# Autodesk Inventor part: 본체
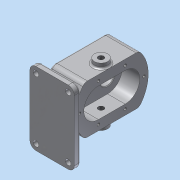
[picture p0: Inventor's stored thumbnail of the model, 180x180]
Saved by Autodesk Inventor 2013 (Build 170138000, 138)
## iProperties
Created: 2019-03
Part Number: 본체
Material: 알루미늄 6061
Document SubType Name: Modeling
Designer: Administrator
Mass: 1194.85 g
Surface Area: 724.416 cm^2
Volume: 440.905 cm^3
Density: 2.71 g/cm^3
Author: Administrator
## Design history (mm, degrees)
sketch "스케치1"
  geometry: L1 (26.5, -60)-(-26.5, -60); L2 (-36.5, -50)-(-36.5, 50); L3 (-26.5, 60)-(26.5, 60); L4 (36.5, 50)-(36.5, -50); A1 r 10 centre (26.5, -50) between (26.5, -60) and (36.5, -50); A2 r 10 centre (26.5, 50) between (36.5, 50) and (26.5, 60); A3 r 10 centre (-26.5, 50) between (-26.5, 60) and (-36.5, 50); A4 r 10 centre (-26.5, -50) between (-36.5, -50) and (-26.5, -60); 6 further points
  constraints: 8 end point, 8 point on circle, 8 tangent, 6 point on line, 4 centre point, 3 equal radius, 2 midpoint, 2 parallel, 1 horizontal, 1 horizontal alignment, 1 perpendicular, 1 vertical alignment
  dimensions: "d0" = 73 distance of point (-36.5, 60) point (36.5, 60); "d1" = 120 distance of point (-36.5, -60) point (-36.5, 60); "d2" = 10 radius of A1
extrude "돌출1" new body sketch "스케치1" distance "d4" = 10; taper "d5" = 0 deg
hole "구멍1" diameter "d8" = 9; stored, may be unused: countersink angle "d12" = 90 deg, drill point angle "d14" = 118 deg; dims "d6" = 10, "d7" = 10, "d9" = 6, "d10" = 4, "d11" = 2, "d13" = 8
hole "구멍2" diameter "d17" = 9; stored, may be unused: countersink angle "d21" = 90 deg, drill point angle "d23" = 118 deg; dims "d15" = 10, "d16" = 10, "d18" = 6, "d19" = 4, "d20" = 2, "d22" = 8
sketch "스케치2"
  geometry: L1 (36.5, -50)-(36.5, 50) reference; 2 further points
  constraints: 1 horizontal alignment, 1 other
  dimensions: "d24" = 10 distance from line of L1 point (26.5, 0)
feature "엠보싱1" sketch "스케치2" dims "d0" = 73, "d1" = 120, "d2" = 10, "d18" = 6, "d25" = 0.5, "d26" = 0
sketch "스케치3"
  geometry: L1 (24.115, 10.5)-(24.529, 10.5) reference; L2 (24.529, 10.5)-(24.529, 10) reference; L3 (24.529, 10)-(36.5, 10) reference; L4 (36.5, 10)-(36.5, 0) reference; L5 (36.5, 0)-(-36.5, 0) reference; L6 (-36.5, 0)-(-36.5, 10) reference; L7 (-36.5, 10)-(24.115, 10) reference; L8 (24.115, 10)-(24.115, 10.5) reference; L9 (-36.5, 10)-(6.5, 10); L10 (6.5, 10)-(6.5, 25); L11 (6.5, 25)-(-36.5, 25); L12 (-36.5, 25)-(-36.5, 10); 1 further point
  constraints: 8 end point, 2 parallel, 1 horizontal, 1 perpendicular
  dimensions: "d27" = 43 distance of L11.end L10.end; "d42" = 15 distance of L9.end L10.end
extrude "돌출2" join sketch "스케치3" distance "d28" = 6; taper "d30" = 0 deg; dims "d29" = 6, "d31" = 0
fillet "모깎기1" dims "d32" = 6
fillet "모깎기2" dims "d33" = 3
sketch "스케치4"
  geometry: L1 (0, 0)-(100, 0) reference; L2 (44, 25)-(56, 25) reference; L3 (90, 121.704)-(90, 41.704); L4 (10, 41.704)-(10, 121.704); A1 r 60 centre (50, 81.704) between (86, 129.704) and (14, 129.704); A2 r 10 centre (20, 121.704) between (14, 129.704) and (10, 121.704); A3 r 10 centre (80, 121.704) between (90, 121.704) and (86, 129.704); A4 r 10 centre (20, 41.704) between (10, 41.704) and (14, 33.704); A5 r 60 centre (50, 81.704) between (14, 33.704) and (86, 33.704); A6 r 10 centre (80, 41.704) between (86, 33.704) and (90, 41.704); 6 further points
  constraints: 13 point on circle, 6 centre point, 4 end point, 4 tangent, 2 midpoint, 1 coincident, 1 equal radius, 1 parallel
  dimensions: "d36" = 120 diameter of A1; "d37" = 10 radius of A2
extrude "돌출3" join sketch "스케치4" distance "d40" = 53; taper "d41" = 0 deg
fillet "모깎기3" dims "d43" = 3
fillet "모깎기4" dims "d44" = 3
sketch "스케치5"
  geometry: L1 (-26, 103.704)-(-26, 59.704); L2 (-74, 59.704)-(-74, 103.704); L3 (-100, 0)-(0, 0) reference; A1 r 24 centre (-50, 103.704) between (-26, 103.704) and (-74, 103.704); A2 r 24 centre (-50, 59.704) between (-74, 59.704) and (-26, 59.704); A3 r 60 centre (-50, 81.704) between (-86, 33.704) and (-14, 33.704) reference; 4 further points
  constraints: 4 end point, 4 point on circle, 3 midpoint, 2 centre point, 1 parallel, 1 vertical alignment
  dimensions: "d47" = 44 distance of L1.end L1.start; "d48" = 24 radius of A1; "d49" = 24 radius of A2; "d51" = 48 distance between parallel lines of L1 L2; "d92" = 22 distance of A1.centre A3.centre
extrude "돌출4" cut sketch "스케치5" distance "d54" = 29; taper "d55" = 0 deg
hole "구멍3" diameter "d59" = 25; stored, may be unused: countersink angle "d63" = 90 deg, drill point angle "d65" = 0 deg; dims "d57" = 10, "d58" = 10, "d60" = 6, "d61" = 4, "d62" = 2, "d64" = 15
hole "구멍4" diameter "d68" = 25; stored, may be unused: countersink angle "d72" = 90 deg, drill point angle "d74" = 0 deg; dims "d66" = 10, "d67" = 10, "d69" = 6, "d70" = 4, "d71" = 2, "d73" = 15
chamfer "모따기1" distance "d75" = 1; stored, may be unused: second distance "d76" = 2, angle "d77" = 45 deg
sketch "스케치6"
  geometry: L1 (-10, 41.704)-(-10, 121.704) reference; L2 (-50, 103.704)-(-81, 103.704); A1 r 24 centre (-50, 103.704) between (-26, 103.704) and (-74, 103.704) reference; 1 further point
  constraints: 2 end point, 1 coincident, 1 perpendicular
hole "구멍5" sketch "스케치6" at (-81, 103.704) diameter "d80" = 4.459; stored, may be unused: countersink angle "d84" = 90 deg, drill point angle "d86" = 118 deg; dims "d81" = 10, "d82" = 4, "d83" = 2, "d85" = 12
sketch "스케치8"
  geometry: L1 (-10, 41.704)-(-10, 121.704) reference; L2 (-50, 59.704)-(-81, 59.704); A1 r 24 centre (-50, 59.704) between (-74, 59.704) and (-26, 59.704) reference; 1 further point
  constraints: 2 end point, 1 perpendicular
  dimensions: "d95" = 31 distance of L2.start L2.end
hole "구멍6" sketch "스케치8" at (-81, 59.704) diameter "d96" = 4.459; stored, may be unused: countersink angle "d100" = 90 deg, drill point angle "d102" = 118 deg; dims "d97" = 10, "d98" = 4, "d99" = 2, "d101" = 12
sketch "스케치9"
  geometry: L1 (50, 81.704)-(72, 81.704); C1 r 19 at (50, 103.704); A1 r 57 centre (50, 81.704) between (15.8, 36.104) and (41.857, 25.288) reference; 1 further point
  constraints: 2 end point, 1 centre point, 1 horizontal
  dimensions: "d108" = 38 diameter of C1
extrude "돌출5" join sketch "스케치9" distance "d109" = 17; taper "d110" = 0 deg
fillet "모깎기5" dims "d111" = 3
hole "구멍7" diameter "d114" = 17; stored, may be unused: countersink angle "d118" = 90 deg, drill point angle "d120" = 0 deg; dims "d112" = 10, "d113" = 10, "d115" = 10, "d116" = 28, "d117" = 7.3, "d119" = 26
chamfer "모따기2" distance "d121" = 0.7; stored, may be unused: second distance "d122" = 2, angle "d123" = 30 deg
fillet "모깎기6" dims "d124" = 0.5
sketch "스케치11"
  geometry: L1 (-43, -41.704)-(10, -41.704) reference; L2 (0, 80)-(0, 0) reference; C1 r 11 at (-14, 36.296); 1 further point
  constraints: 1 centre point
  dimensions: "d125" = 22 diameter of C1; "d127" = 78 distance from line of L1 C1.centre; "d131" = 14 distance from line of L2 C1.centre
extrude "돌출6" join sketch "스케치11" distance "d128" = 8; taper "d129" = 0 deg
fillet "모깎기7" dims "d130" = 3
hole "구멍8" diameter "d134" = 8.917; stored, may be unused: countersink angle "d138" = 90 deg, drill point angle "d140" = 118 deg; dims "d132" = 10, "d133" = 10, "d135" = 10, "d136" = 28, "d137" = 7.3, "d139" = 26
fillet "모깎기8" dims "d141" = 3
node "솔리드1"
mirror "대칭1"
pattern_circular "원형 패턴1" dims angle "d88" = 180 deg
pattern_circular "원형 패턴2" dims angle "d104" = -180 deg
mirror "대칭3"
node "절단 모서리 투영1"
